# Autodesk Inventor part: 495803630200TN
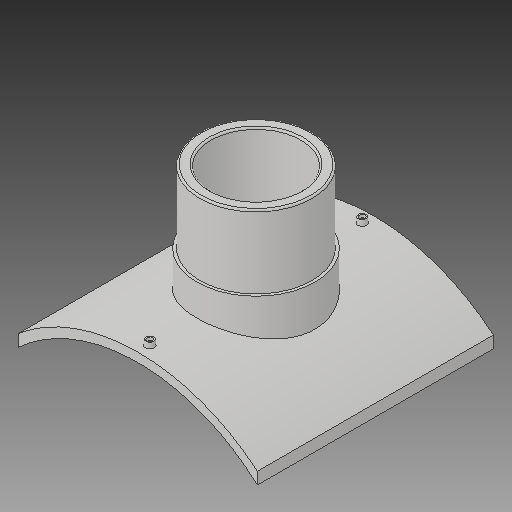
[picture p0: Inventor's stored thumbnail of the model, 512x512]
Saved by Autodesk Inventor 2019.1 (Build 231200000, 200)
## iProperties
Created: 2017-10
Part Number: 495803630200TN
Material: Generic
Description: PLASSON BRANCH SADDLE  630x185
Document SubType Name: Modeling
Designer: KIM
Mass: 2754.05 g
Surface Area: 3037.44 cm^2
Volume: 2754.05 cm^3
Density: 1 g/cm^3
Appearance: Default
Author: KIM
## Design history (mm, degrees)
derived "495803.ipt"
feature "Solid1::495803.ipt"
tag "TaggingFeature1"
body "Solid1"
other parameters: "d1" = 16, "d2" = 425, "d4" = 0, "d12" = 340.6, "d13" = 14, "d14" = 189, "d16" = 5 deg, "d18" = 4, "d19" = 14, "d20" = 0, "d21" = 3, "d22" = 0, "d23" = 516, "d25" = 16, "d28" = 0, "d29" = 9.6, "d31" = 0, "d32" = 92.5, "d33" = 0, "d34" = 6.3, "d37" = 129.5, "d38" = 0, "d39" = 3.15, "B_" = 425, "H_" = 185, "x_" = 16, "D_" = 16
